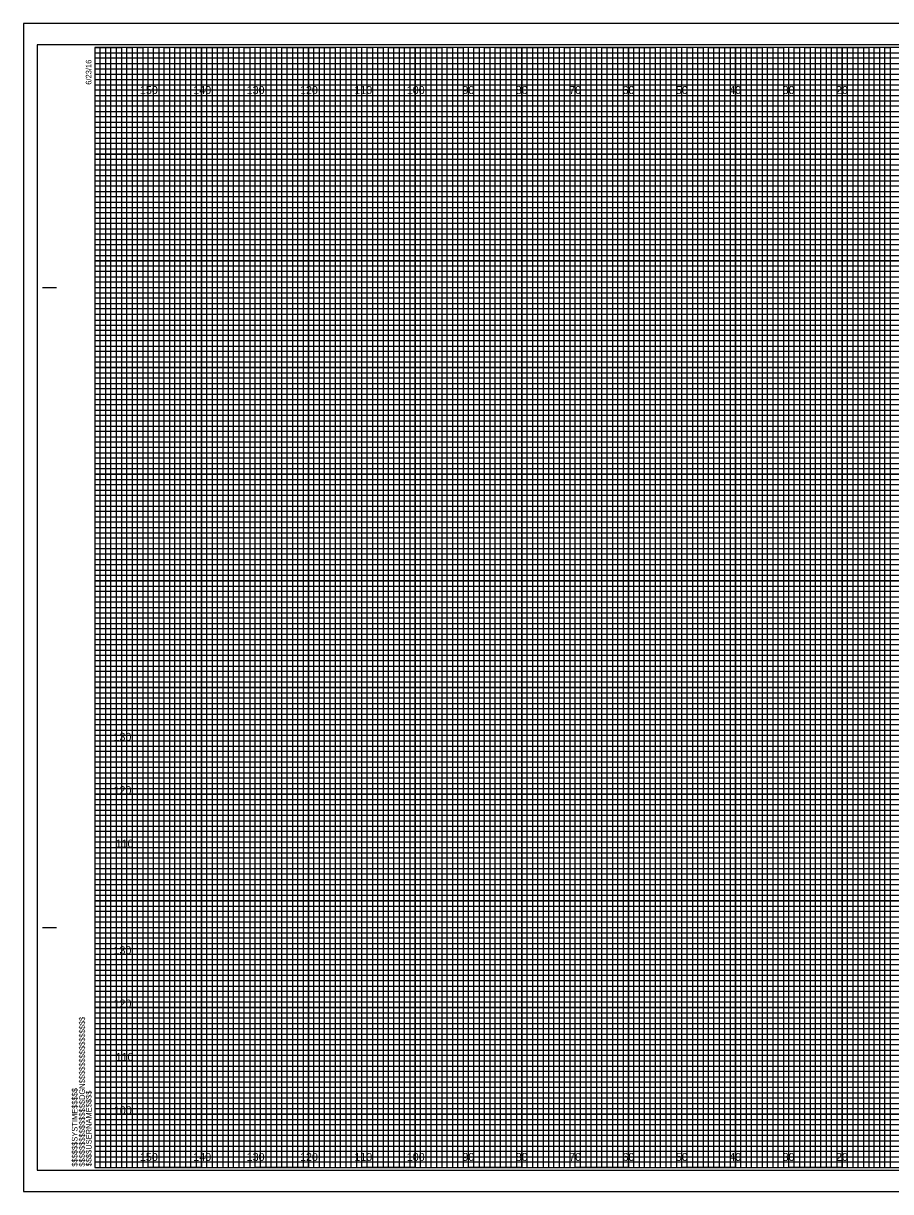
# Model space of a CAD drawing. Extents: x -13 to 323, y -5 to 1754.
# Drawn here: x -13.4 to 149.1, y 1535.5 to 1754.5 of the extents above; entities that cross this region are included whole.
import ezdxf

# ---------------------------------------------------------------- set-up
doc = ezdxf.new("R2010")
doc.units = 0
for name, color, linetype in [('Exist Cross Section Cell', 7, 'Continuous'), ('Exist XS Center Line Elevation Label', 7, 'Continuous'), ('Exist XS Ground Line', 7, 'Continuous'), ('Prop CMT Pvmt Course 1', 7, 'Continuous'), ('Prop CMT Pvmt Course 3', 7, 'Continuous'), ('Prop CMT Pvmt Surface', 7, 'Continuous'), ('Prop CMT Pvmt Surface Shoulder', 7, 'Continuous'), ('Prop CMT Shld Paved Course 1', 7, 'Continuous'), ('Prop CMT Shld Paved Course 2', 7, 'Continuous'), ('Prop CMT Shld Paved Course 3', 7, 'Continuous'), ('Prop CMT Subgrade Earthwork', 7, 'Continuous')]:
    doc.layers.add(name, color=color, linetype=linetype)

msp = doc.modelspace()

# ---------------------------------------------------------------- linework, layer by layer
at = {"layer": 'Exist XS Center Line Elevation Label'}
for points in [[(0, 1750), (5, 1750), (5, 1540), (15, 1540), (15, 1750), (25, 1750), (25, 1540), (35, 1540), (35, 1750), (45, 1750), (45, 1540), (55, 1540), (55, 1750), (65, 1750), (65, 1540), (75, 1540), (75, 1750), (85, 1750), (85, 1540), (95, 1540), (95, 1750), (105, 1750), (105, 1540), (115, 1540), (115, 1750), (125, 1750), (125, 1540), (135, 1540), (135, 1750), (145, 1750), (145, 1540), (155, 1540)], [(0, 1745), (275, 1745)], [(0, 1725), (320, 1725), (320, 1735), (0, 1735)], [(0, 1705), (320, 1705), (320, 1715), (0, 1715)], [(0, 1685), (320, 1685), (320, 1695), (0, 1695)], [(0, 1665), (320, 1665), (320, 1675), (0, 1675)], [(0, 1645), (320, 1645), (320, 1655), (0, 1655)], [(0, 1625), (320, 1625), (320, 1635), (0, 1635)], [(0, 1605), (320, 1605), (320, 1615), (0, 1615)], [(0, 1585), (320, 1585), (320, 1595), (0, 1595)], [(0, 1565), (320, 1565), (320, 1575), (0, 1575)], [(0, 1545), (320, 1545), (320, 1555), (0, 1555)]]:
    msp.add_lwpolyline(points, dxfattribs=at)
at = {"layer": 'Exist XS Ground Line'}
for p, q in [((10, 1750), (0, 1750)), ((10, 1540), (10, 1750)), ((30, 1750), (20, 1750)), ((20, 1750), (20, 1540)), ((30, 1540), (30, 1750)), ((50, 1750), (40, 1750)), ((40, 1750), (40, 1540)), ((50, 1540), (50, 1750)), ((70, 1750), (60, 1750)), ((60, 1750), (60, 1540)), ((70, 1540), (70, 1750)), ((90, 1750), (80, 1750)), ((80, 1750), (80, 1540)), ((90, 1540), (90, 1750)), ((110, 1750), (100, 1750)), ((100, 1750), (100, 1540)), ((110, 1540), (110, 1750)), ((130, 1750), (120, 1750)), ((120, 1750), (120, 1540)), ((130, 1540), (130, 1750)), ((150, 1750), (140, 1750)), ((140, 1750), (140, 1540)), ((20, 1540), (10, 1540)), ((40, 1540), (30, 1540)), ((60, 1540), (50, 1540)), ((80, 1540), (70, 1540)), ((100, 1540), (90, 1540)), ((120, 1540), (110, 1540)), ((140, 1540), (130, 1540))]:
    msp.add_line(p, q, dxfattribs=at)
for points in [[(0, 1740), (320, 1740), (320, 1730), (0, 1730)], [(0, 1720), (320, 1720), (320, 1710), (0, 1710)], [(0, 1700), (320, 1700), (320, 1690), (0, 1690)], [(0, 1680), (320, 1680), (320, 1670), (0, 1670)], [(0, 1660), (320, 1660), (320, 1650), (0, 1650)], [(0, 1640), (320, 1640), (320, 1630), (0, 1630)], [(0, 1620), (320, 1620), (320, 1610), (0, 1610)], [(0, 1600), (320, 1600), (320, 1590), (0, 1590)], [(0, 1580), (320, 1580), (320, 1570), (0, 1570)], [(0, 1560), (320, 1560), (320, 1550), (0, 1550)]]:
    msp.add_lwpolyline(points, dxfattribs=at)
at = {"layer": 'Prop CMT Pvmt Course 3'}
msp.add_lwpolyline([(-13.4, 1535.5), (323.3, 1535.5), (323.3, 1754.5), (-13.4, 1754.5)], close=True, dxfattribs=at)
at = {"layer": 'Prop CMT Pvmt Surface'}
for p, q in [((10, 1540), (10, 1750)), ((20, 1540), (20, 1750)), ((30, 1540), (30, 1750)), ((40, 1540), (40, 1750)), ((50, 1540), (50, 1750)), ((60, 1540), (60, 1750)), ((70, 1540), (70, 1750)), ((80, 1540), (80, 1750)), ((90, 1540), (90, 1750)), ((100, 1540), (100, 1750)), ((110, 1540), (110, 1750)), ((120, 1540), (120, 1750)), ((130, 1540), (130, 1750)), ((140, 1540), (140, 1750)), ((0, 1740), (320, 1740)), ((0, 1730), (320, 1730)), ((0, 1720), (320, 1720)), ((0, 1710), (320, 1710)), ((0, 1700), (320, 1700)), ((0, 1690), (320, 1690)), ((0, 1680), (320, 1680)), ((0, 1670), (320, 1670)), ((0, 1660), (320, 1660)), ((0, 1650), (320, 1650)), ((0, 1640), (320, 1640)), ((0, 1630), (320, 1630)), ((0, 1620), (320, 1620)), ((0, 1610), (320, 1610)), ((0, 1600), (320, 1600)), ((0, 1590), (320, 1590)), ((0, 1580), (320, 1580)), ((0, 1570), (320, 1570)), ((0, 1560), (320, 1560)), ((0, 1550), (320, 1550))]:
    msp.add_line(p, q, dxfattribs=at)
at = {"layer": 'Prop CMT Pvmt Surface Shoulder'}
for p, q in [((323.3, 1754.5), (-13.4, 1754.5)), ((-13.4, 1754.5), (-13.4, 1535.5)), ((-13.4, 1535.5), (323.3, 1535.5))]:
    msp.add_line(p, q, dxfattribs=at)
at = {"layer": 'Prop CMT Shld Paved Course 1'}
for p, q in [((0, 1749), (260, 1749)), ((260, 1747.98), (0, 1747.98)), ((0, 1747.98), (0, 1747)), ((0, 1747), (260, 1747)), ((260, 1745.89), (0, 1745.89)), ((0, 1745.89), (0, 1744)), ((0, 1744), (320, 1744))]:
    msp.add_line(p, q, dxfattribs=at)
for points in [[(0, 1743), (270, 1743), (320, 1743), (320, 1742), (0, 1742)], [(0, 1741), (320, 1741), (320, 1739), (0, 1739)], [(0, 1738), (320, 1738), (320, 1737), (0, 1736.98)], [(0, 1736), (320, 1736), (320, 1734), (0, 1734)], [(0, 1733), (320, 1733), (320, 1732), (0, 1732)], [(0, 1731), (320, 1731), (320, 1729), (0, 1729)], [(0, 1728), (320, 1728), (320, 1727), (0, 1727)], [(0, 1726), (320, 1726), (320, 1724), (0, 1724)], [(0, 1723), (320, 1723), (320, 1722), (0, 1722)], [(0, 1721), (320, 1721), (320, 1719), (0, 1719)], [(0, 1718), (320, 1718), (320, 1717), (0, 1717)], [(0, 1716), (320, 1716), (320, 1713.95), (320, 1713), (320, 1712), (0, 1712)], [(0, 1714), (320, 1714), (320, 1713), (0, 1713)], [(0, 1711), (320, 1711), (320, 1709), (0, 1709.03)], [(0, 1709.03), (320, 1709), (320, 1708), (0, 1708)], [(0, 1707), (320, 1707), (320, 1706), (0, 1706)], [(0, 1704), (320, 1704), (320, 1703), (0, 1703)], [(0, 1702), (320, 1702), (320, 1701), (0, 1701)], [(-0.07, 1698.89), (320, 1698.89), (320, 1697.88), (-0.07, 1697.88)], [(0, 1697), (320, 1697), (320, 1696), (0, 1696)], [(0, 1694), (320, 1694), (320, 1693), (0, 1693)], [(0, 1692), (320, 1692), (320, 1691), (0, 1691)], [(0, 1689), (320, 1689), (320, 1688), (0, 1688)], [(0, 1687), (320, 1687), (320, 1686), (0, 1686)], [(0, 1684), (320, 1684), (320, 1683), (0, 1683)], [(0, 1682), (320, 1682), (320, 1681), (0, 1681)], [(0, 1679), (320, 1679), (319.99, 1677.98), (0, 1678)], [(0, 1677), (320, 1677), (320, 1676), (0, 1676)], [(0, 1674), (320, 1674), (320, 1673), (0, 1673)], [(0, 1672), (320, 1672), (320, 1671), (0, 1671)], [(0, 1669), (320, 1669), (320, 1668), (0, 1668)], [(0, 1667), (320, 1667), (320, 1666), (0, 1666)], [(0, 1664), (320, 1664), (320, 1663), (0, 1663)], [(0, 1662), (320, 1662), (320, 1661), (0, 1661)], [(0, 1659), (320, 1659), (320, 1658), (0, 1658)], [(0, 1656.99), (320.07, 1656.91), (320, 1656), (0, 1656)], [(0, 1654), (320, 1654), (320, 1653), (0, 1653)], [(0, 1652), (320, 1652), (320, 1651), (0, 1651)], [(0, 1649), (320, 1649), (320, 1648), (0, 1648)], [(0, 1647), (320, 1647), (320, 1646), (0, 1646)], [(0, 1644), (320, 1644), (320, 1643), (0, 1643)], [(0, 1642), (320, 1642), (320, 1641), (0, 1641)], [(0, 1639), (320, 1639), (320, 1638), (0, 1638)], [(0, 1637), (320, 1637), (320, 1636), (0, 1636)], [(0, 1634), (320, 1634), (320, 1633), (0, 1633)], [(0, 1632), (320, 1632), (320, 1631), (0, 1631)], [(0, 1629), (320, 1629), (320, 1628), (0, 1628)], [(0, 1627), (320, 1627), (320, 1626), (0, 1626)], [(0, 1624), (320, 1624), (320, 1623), (0, 1623)], [(0, 1622), (320, 1622), (320, 1621), (0, 1621)], [(0, 1619), (320, 1619), (319.99, 1617.98), (0, 1618)], [(0, 1617), (320, 1617), (320, 1616), (0, 1616)], [(0, 1614), (320, 1614), (320, 1613), (0, 1613)], [(0, 1612), (320, 1612), (320, 1611), (0, 1611)], [(0, 1609), (320, 1609), (320, 1608), (0, 1608)], [(0, 1607), (320, 1607), (320, 1606), (0, 1606)], [(0, 1604), (320, 1604), (320, 1603), (0, 1603)], [(0, 1602), (320, 1602), (320, 1601), (0, 1601)], [(0, 1599), (320, 1599), (320, 1598), (0, 1598)], [(0, 1596.99), (320.07, 1596.91), (320, 1596), (0, 1596)], [(0, 1594), (320, 1594), (320, 1593), (0, 1593)], [(0, 1592), (320, 1592), (320, 1591), (0, 1591)], [(0, 1589), (320, 1589), (320, 1588), (0, 1588)], [(0, 1587), (320, 1587), (320, 1586), (0, 1586)], [(0, 1584), (320, 1584), (320, 1583), (0, 1583)], [(0, 1582), (320, 1582), (320, 1581), (0, 1581)], [(0, 1579), (320, 1579), (320, 1578), (0, 1578)], [(0, 1577), (320, 1577), (320, 1576), (0, 1576)], [(0, 1574), (320, 1574), (320, 1573), (0, 1573)], [(0, 1572), (320, 1572), (320, 1571), (0, 1571)], [(0, 1569), (320, 1569), (320, 1568), (0, 1568)], [(0, 1567), (320, 1567), (320, 1566), (0, 1566)], [(0, 1564), (320, 1564), (320, 1563), (0, 1563)], [(0, 1562), (320, 1562), (320, 1561), (0, 1561)], [(0, 1559), (320, 1559), (320, 1558), (0, 1558)], [(0, 1557), (320, 1557), (320, 1556), (0, 1556)], [(0, 1554), (320, 1554), (320, 1553), (0, 1553)], [(0, 1552), (320, 1552), (320, 1551), (0, 1551)], [(0, 1549), (320, 1549), (320, 1548), (0, 1548)], [(0, 1547), (320, 1547), (320, 1546), (0, 1546)], [(0, 1544), (320, 1544), (320, 1543), (0, 1543)], [(0, 1542), (320, 1542), (320, 1541), (0, 1541)]]:
    msp.add_lwpolyline(points, dxfattribs=at)
at = {"layer": 'Prop CMT Shld Paved Course 2'}
for p, q in [((-9.8, 1705), (-7.3, 1705)), ((-9.7, 1705), (-7.2, 1705)), ((-9.8, 1585), (-7.3, 1585)), ((-9.7, 1585), (-7.2, 1585)), ((0, 1540), (0, 1540)), ((0, 1540), (0, 1540)), ((0, 1540), (0, 1540)), ((0, 1540), (0, 1540)), ((0, 1540), (0, 1540)), ((0, 1540), (0, 1540)), ((0, 1540), (0, 1540))]:
    msp.add_line(p, q, dxfattribs=at)
msp.add_lwpolyline([(320, 1750), (0, 1750), (0, 1540), (320, 1540)], close=True, dxfattribs=at)
at = {"layer": 'Prop CMT Shld Paved Course 3'}
for points in [[(0, 1540), (1, 1540), (1, 1750), (2, 1750), (2, 1540)], [(2, 1540), (3, 1540), (3, 1750), (4, 1750), (4, 1540)], [(5, 1540), (6, 1540), (6, 1750), (7, 1750), (7, 1540)], [(7, 1540), (8, 1540), (8, 1750), (9, 1750), (9, 1540)], [(10, 1540), (11, 1540), (11, 1750), (12, 1750), (12, 1540)], [(12, 1540), (13, 1540), (13, 1750), (14, 1750), (14, 1540)], [(15, 1540), (16, 1540), (16, 1750), (17, 1750), (17, 1540)], [(17, 1540), (18, 1540), (18, 1750), (19, 1750), (19, 1540)], [(20, 1540), (21, 1540), (21, 1750), (22, 1750), (22, 1540)], [(22, 1540), (23, 1540), (23, 1750), (24, 1750), (24, 1540)], [(25, 1540), (26, 1540), (26, 1750), (27, 1750), (27, 1540)], [(27, 1540), (28, 1540), (28, 1750), (29, 1750), (29, 1540)], [(30, 1540), (31, 1540), (31, 1750), (32, 1750), (32, 1540)], [(32, 1540), (33, 1540), (33, 1750), (34, 1750), (34, 1540)], [(35, 1540), (36, 1540), (36, 1750), (37, 1750), (37, 1540)], [(37, 1540), (38, 1540), (38, 1750), (39, 1750), (39, 1540)], [(40, 1540), (41, 1540), (41, 1750), (42, 1750), (42, 1540)], [(42, 1540), (43, 1540), (43, 1750), (44, 1750), (44, 1540)], [(45, 1540), (46, 1540), (46, 1750), (47, 1750), (47, 1540)], [(47, 1540), (48, 1540), (48, 1750), (49, 1750), (49, 1540)], [(50, 1540), (51, 1540), (51, 1750), (52, 1750), (52, 1540)], [(52, 1540), (53, 1540), (53, 1750), (54, 1750), (54, 1540)], [(55, 1540), (56, 1540), (56, 1750), (57, 1750), (57, 1540)], [(57, 1540), (58, 1540), (58, 1750), (59, 1750), (59, 1540)], [(60, 1540), (61, 1540), (61, 1750), (62, 1750), (62, 1540)], [(62, 1540), (63, 1540), (63, 1750), (64, 1750), (64, 1540)], [(65, 1540), (66, 1540), (66, 1750), (67, 1750), (67, 1540)], [(67, 1540), (68, 1540), (68, 1750), (69, 1750), (69, 1540)], [(70, 1540), (71, 1540), (71, 1750), (72, 1750), (72, 1540)], [(72, 1540), (73, 1540), (73, 1750), (74, 1750), (74, 1540)], [(75, 1540), (76, 1540), (76, 1750), (77, 1750), (77, 1540)], [(77, 1540), (78, 1540), (78, 1750), (79, 1750), (79, 1540)], [(80, 1540), (81, 1540), (81, 1750), (82, 1750), (82, 1540)], [(82, 1540), (83, 1540), (83, 1750), (84, 1750), (84, 1540)], [(85, 1540), (86, 1540), (86, 1750), (87, 1750), (87, 1540)], [(87, 1540), (88, 1540), (88, 1750), (89, 1750), (89, 1540)], [(90, 1540), (91, 1540), (91, 1750), (92, 1750), (92, 1540)], [(92, 1540), (93, 1540), (93, 1750), (94, 1750), (94, 1540)], [(95, 1540), (96, 1540), (96, 1750), (97, 1750), (97, 1540)], [(97, 1540), (98, 1540), (98, 1750), (99, 1750), (99, 1540)], [(100, 1540), (101, 1540), (101, 1750), (102, 1750), (102, 1540)], [(102, 1540), (103, 1540), (103, 1750), (104, 1750), (104, 1540)], [(105, 1540), (106, 1540), (106, 1750), (107, 1750), (107, 1540)], [(107, 1540), (108, 1540), (108, 1750), (109, 1750), (109, 1540)], [(110, 1540), (111, 1540), (111, 1750), (112, 1750), (112, 1540)], [(112, 1540), (113, 1540), (113, 1750), (114, 1750), (114, 1540)], [(115, 1540), (116, 1540), (116, 1750), (117, 1750), (117, 1540)], [(117, 1540), (118, 1540), (118, 1750), (119, 1750), (119, 1540)], [(120, 1540), (121, 1540), (121, 1750), (122, 1750), (122, 1540)], [(122, 1540), (123, 1540), (123, 1750), (124, 1750), (124, 1540)], [(125, 1540), (126, 1540), (126, 1750), (127, 1750), (127, 1540)], [(127, 1540), (128, 1540), (128, 1750), (129, 1750), (129, 1540)], [(130, 1540), (131, 1540), (131, 1750), (132, 1750), (132, 1540)], [(132, 1540), (133, 1540), (133, 1750), (134, 1750), (134, 1540)], [(135, 1540), (136, 1540), (136, 1750), (137, 1750), (137, 1540)], [(137, 1540), (138, 1540), (138, 1750), (139, 1750), (139, 1540)], [(140, 1540), (141, 1540), (141, 1750), (142, 1750), (142, 1540)], [(142, 1540), (143, 1540), (143, 1750), (144, 1750), (144, 1540)], [(145, 1540), (146, 1540), (146, 1750), (147, 1750), (147, 1540)], [(147, 1540), (148, 1540), (148, 1750), (149, 1750), (149, 1540)]]:
    msp.add_lwpolyline(points, dxfattribs=at)
at = {"layer": 'Prop CMT Subgrade Earthwork'}
msp.add_lwpolyline([(-10.8, 1539.5), (322.4, 1539.5), (322.4, 1750.5), (-10.8, 1750.5)], close=True, dxfattribs=at)

# ---------------------------------------------------------------- texts
at = {"layer": 'Exist Cross Section Cell'}
for s, p in [('150', (8.44, 1741.25)), ('140', (18.44, 1741.25)), ('130', (28.44, 1741.25)), ('120', (38.44, 1741.25)), ('110', (48.62, 1741.25)), ('100', (58.44, 1741.25)), ('90', (68.86, 1741.25)), ('80', (78.86, 1741.25)), ('70', (88.86, 1741.25)), ('60', (98.86, 1741.25)), ('50', (108.86, 1741.25)), ('40', (118.86, 1741.25)), ('30', (128.86, 1741.25)), ('20', (138.86, 1741.25)), ('150', (8.44, 1541.25)), ('140', (18.44, 1541.25)), ('130', (28.44, 1541.25)), ('120', (38.44, 1541.25)), ('110', (48.62, 1541.25)), ('100', (58.44, 1541.25)), ('90', (68.86, 1541.25)), ('80', (78.86, 1541.25)), ('70', (88.86, 1541.25)), ('60', (98.86, 1541.25)), ('50', (108.86, 1541.25)), ('40', (118.86, 1541.25)), ('30', (128.86, 1541.25)), ('20', (138.86, 1541.25))]:
    msp.add_text(s, height=1.5, dxfattribs=at).set_placement(p)
at = {"layer": 'Prop CMT Pvmt Course 1'}
for s, p in [('130', (3.49, 1620)), ('120', (3.5, 1610)), ('110', (3.88, 1600)), ('130', (3.49, 1580)), ('120', (3.5, 1570)), ('110', (3.88, 1560)), ('100', (3.55, 1550))]:
    msp.add_text(s, height=1.5, dxfattribs=at).set_placement(p)
at = {"layer": 'Prop CMT Shld Paved Course 2'}
for s, p in [('6/23/16', (-0.65, 1743)), ('$$$$$$$$$$$$$$$$DGN$$$$$$$$$$$$$$$$', (-1.88, 1540.18)), ('$$$$$$SYSTIME$$$$$', (-3.26, 1540.18)), ('$$$$USERNAME$$$$', (-0.62, 1540.23))]:
    msp.add_text(s, height=1.05, rotation=90, dxfattribs=at).set_placement(p)

doc.saveas('drawing.dxf')
